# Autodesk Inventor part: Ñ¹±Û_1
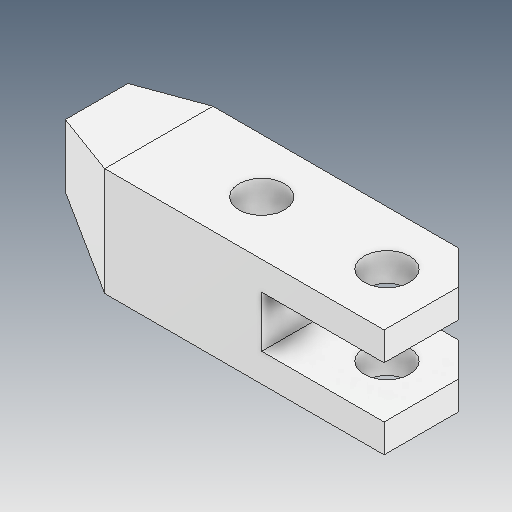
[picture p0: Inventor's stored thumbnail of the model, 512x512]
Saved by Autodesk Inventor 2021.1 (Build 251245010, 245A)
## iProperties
Created: 2021-05
Part Number: Ñ¹±Û_1
Material: Ogólny
Document SubType Name: Modeling
Designer: user
Density: 1 g/cm^3
Appearance: Domyślna
Author: user
Revision Number: ÈÎºÎ
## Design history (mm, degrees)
feature "ÊäÈë1"
node "Bryła1"
